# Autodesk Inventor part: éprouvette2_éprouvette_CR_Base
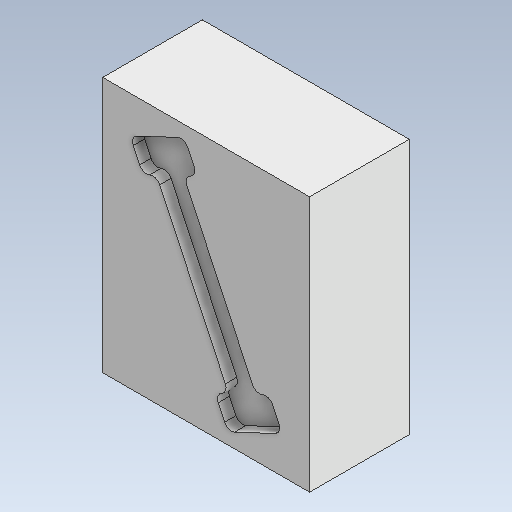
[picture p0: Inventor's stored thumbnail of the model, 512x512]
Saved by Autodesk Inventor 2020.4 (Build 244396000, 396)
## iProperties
Created: 2021-10
Part Number: éprouvette2_éprouvette_CR_Base
Material: Générique
Document SubType Name: Modeling
Designer: mel
Density: 1 g/cm^3
Appearance: Par défaut
Author: mel
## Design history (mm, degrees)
node "éprouvette2_éprouvette_MP"
feature "Solide3::éprouvette2_éprouvette_MP"
tag "FonctionRepérage1"
node "Solide1"
feature "éprouvette2_éprouvette_MP_Corps"
